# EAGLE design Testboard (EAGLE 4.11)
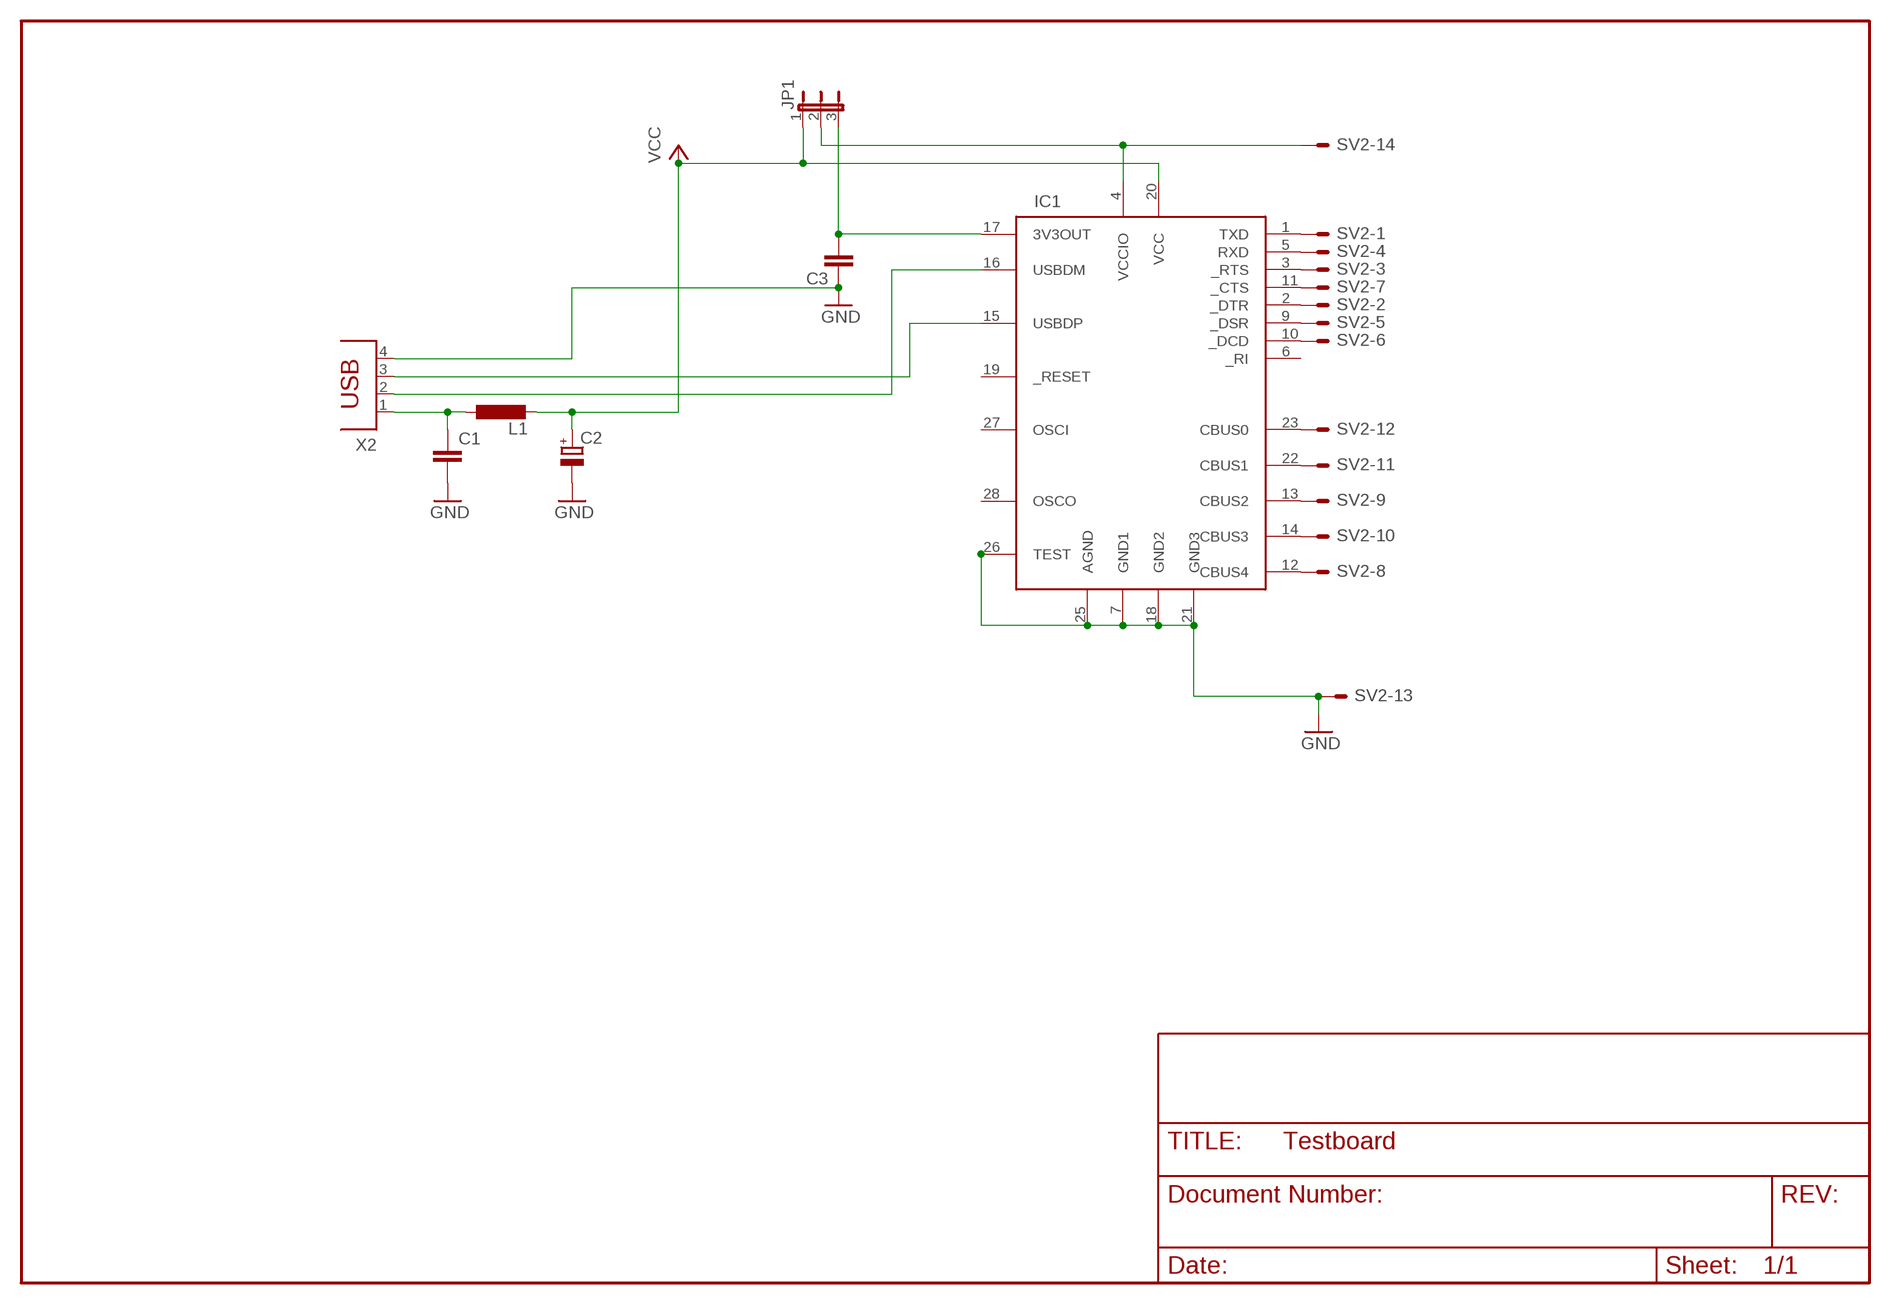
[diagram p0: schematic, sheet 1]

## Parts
C1  C-EUC0805  [C0805]
C2  CPOL-EUE2.5-6  [E2,5-6]
C3  C-EUC0805  [C0805]
IC1  FT232RL  [SSOP28DB]
JP1  JP2E  [JP2]
L1  L-EU0204/7  [0204/7]
SV2  ML14LE  [ML14L]
X2  PN61729  [PN61729]

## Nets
GND: C1.2 C2.- C3.1 IC1.7(GND1) IC1.18(GND2) IC1.21(GND3) IC1.25(AGND) IC1.26(TEST) SV2.13 X2.4
N$1: IC1.1(TXD) SV2.1
N$2: IC1.2(_DTR) SV2.2
N$3: C3.2 IC1.17(3V3OUT) JP1.3
N$4: IC1.16(USBDM) X2.2
N$5: IC1.15(USBDP) X2.3
N$6: IC1.3(_RTS) SV2.3
N$7: IC1.5(RXD) SV2.4
N$8: IC1.9(_DSR) SV2.5
N$9: IC1.10(_DCD) SV2.6
N$10: IC1.11(_CTS) SV2.7
N$11: IC1.12(CBUS4) SV2.8
N$12: IC1.13(CBUS2) SV2.9
N$13: IC1.14(CBUS3) SV2.10
N$14: IC1.22(CBUS1) SV2.11
N$15: IC1.23(CBUS0) SV2.12
N$16: C1.1 L1.1 X2.1
N$17: IC1.4(VCCIO) JP1.2 SV2.14
VCC: C2.+ IC1.20(VCC) JP1.1 L1.2
Unconnected: IC1.6(_RI) IC1.19(_RESET) IC1.27(OSCI) IC1.28(OSCO)

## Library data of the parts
C1 C3 = rcl:C-EU: CAPACITOR, European symbol
C2 = rcl:CPOL-EU: POLARIZED CAPACITOR, European symbol
IC1 = ftdichip:FT232RL: USB UART 4th Generation USB UART (USB <-> Serial) Controller
JP1 = jumper:JP2E: JUMPER
L1 = rcl:L-EU: INDUCTOR, European symbol
SV2 = con-ml:ML14LE: HARTING
X2 = con-berg:PN61729: BERG USB connector

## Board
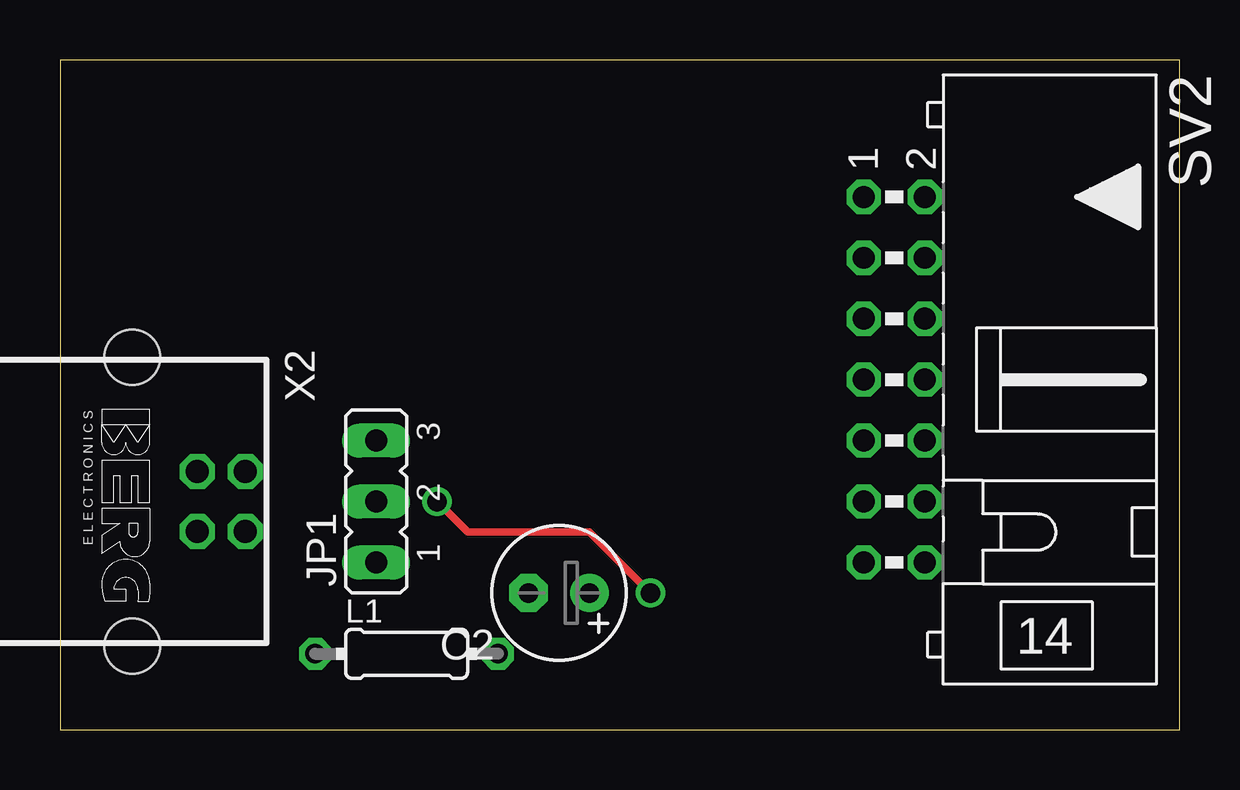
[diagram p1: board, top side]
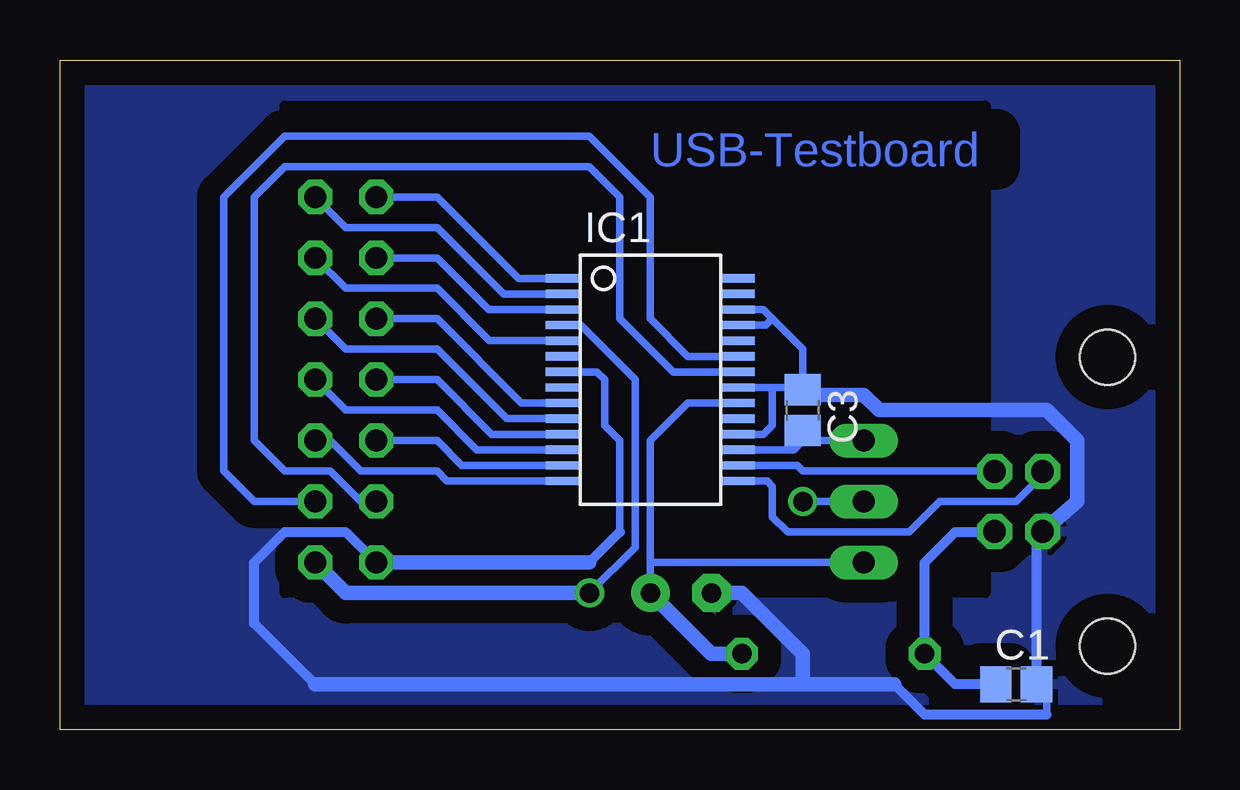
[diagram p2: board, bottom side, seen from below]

Size 46.66 x 27.93 mm. Coordinates in mm from the lower left corner, seen from the top.
Outline: 0,0 46.66,0 46.66,27.93 0,27.93 0,0
Copper layers (1*16): Top 0.035mm / dielectric 1.5mm / Bottom 0.035mm
Design rules "default": minimum track width 10mil, minimum drill 24mil, track to track 38mil, track to pad 38mil, pad to pad 38mil, via to via 38mil, smd to smd 38mil, copper to edge 40mil, drill to drill 8mil, minimum pad ring 10mil, minimum via ring 8mil, stop-mask expansion 4mil, vias tented up to drill 0mil, thermal gap 10mil
bRestrict: area 8.1,5.7 to 37.3,26

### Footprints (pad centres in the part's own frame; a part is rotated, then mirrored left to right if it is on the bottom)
C0805 = smd 1.3 x 1.5: 1 -0.85,0; 2 0.85,0
E2,5-6 = drill 0.813 pad 1.6 round: + -1.27,0 | drill 0.813 pad 1.6 octagon: - 1.27,0
SSOP28DB = smd 0.348 x 1.397: 1 -4.225,-3.656; 2 -3.575,-3.656; 3 -2.925,-3.656; 4 -2.275,-3.656; 5 -1.625,-3.656; 6 -0.975,-3.656; 7 -0.325,-3.656; 8 0.325,-3.656; 9 0.975,-3.656; 10 1.625,-3.656; 11 2.275,-3.656; 12 2.925,-3.656; 13 3.575,-3.656; 14 4.225,-3.656; 15 4.225,3.656; 16 3.575,3.656; 17 2.925,3.656; 18 2.275,3.656; 19 1.625,3.656; 20 0.975,3.656; 21 0.325,3.656; 22 -0.325,3.656; 23 -0.975,3.656; 24 -1.625,3.656; 25 -2.275,3.656; 26 -2.925,3.656; 27 -3.575,3.656; 28 -4.225,3.656
JP2 = drill 0.914 long: 1 -2.54,0; 2 0,0; 3 2.54,0
0204/7 = drill 0.813 octagon: 1 -3.81,0; 2 3.81,0
ML14L = drill 0.914 octagon: 1 -7.62,-1.27; 2 -7.62,1.27; 3 -5.08,-1.27; 4 -5.08,1.27; 5 -2.54,-1.27; 6 -2.54,1.27; 7 0,-1.27; 8 0,1.27; 9 2.54,-1.27; 10 2.54,1.27; 11 5.08,-1.27; 12 5.08,1.27; 13 7.62,-1.27; 14 7.62,1.27
PN61729 = drill 0.95 octagon: 1 1.25,4.71; 2 -1.25,4.71; 3 -1.25,2.71; 4 1.25,2.71 | hole 2.3: -6.02,0; 6.02,0

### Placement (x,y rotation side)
C1  6.82,1.9 0 bottom
C2  20.79,5.71 180 top
C3  15.71,13.33 270 bottom
IC1  22.06,14.6 270 bottom
JP1  13.17,9.52 90 top
L1  14.44,3.17 0 top
SV2  34.76,14.6 270 top
X2  3.01,9.52 270 top

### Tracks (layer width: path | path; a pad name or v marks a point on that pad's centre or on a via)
GND
  Bottom 0.305: 16.98,17.14 15.71,15.87 15.71,14.6 16.04,14.28 16.98,14.28 | 23.33,8.25 23.33,12.06 23.96,12.7 23.96,14.6 24.29,14.93 IC1.7 | IC1.26 17.36,17.52 16.98,17.14 | IC1.25 17.24,16.88 16.98,17.14 | 16.98,14.28 IC1.21 | IC1.18 17.35,12.33 16.98,12.7 16.98,14.28 | 5.55,0.63 5.55,1.9
  Bottom 0.406: X2.4 5.57,8.27 5.55,8.25 5.97,7.83 C1.2 | 24.6,6.98 23.33,8.25 | SV2.13 34.76,8.25 37.3,8.25 38.57,6.98 38.57,4.44 36.03,1.9 | 5.55,0.63 10.63,0.63 11.9,1.9
  Bottom 0.61: X2.4 4.28,9.52 4.28,12.06 5.55,13.33 12.54,13.33 13.17,13.97 15.71,13.97 C3.1 15.71,14.6 | SV2.13 24.6,6.98 | 11.9,1.9 15.71,1.9 | 15.71,1.9 36.03,1.9 | C2.- 18.25,5.71 15.71,3.17 15.71,1.9
  pour Bottom: 0.47,27.3 0.47,0.63 46.19,0.63 46.19,27.3
N$1
  Bottom 0.305: IC1.1 27.55,18.82 30.95,22.22 SV2.1
N$2
  Bottom 0.305: IC1.2 28.17,18.18 30.95,20.95 34.76,20.95 SV2.2
N$3
  Bottom 0.305: IC1.17 16.09,11.68 15.71,12.06 | 15.71,12.06 C3.2 | JP1.3 15.71,12.06
N$4
  Bottom 0.305: IC1.16 15.95,11.03 15.71,10.79 8.09,10.79 8.07,10.77 X2.2
N$5
  Bottom 0.305: 5.57,10.77 5.55,10.79 | X2.3 5.57,10.77 | 5.57,10.77 6.82,9.52 10,9.52 11.27,8.25 16.34,8.25 16.98,8.89 16.98,10.16 17.2,10.38 IC1.15
N$6
  Bottom 0.305: IC1.3 28.79,17.52 30.95,19.68 SV2.3
N$7
  Bottom 0.305: IC1.5 28.77,16.23 30.95,18.41 34.76,18.41 SV2.4
N$8
  Bottom 0.305: IC1.9 27.43,13.62 30.95,17.14 SV2.5
N$9
  Bottom 0.305: IC1.10 28.05,12.98 30.95,15.87 34.76,15.87 SV2.6
N$10
  Bottom 0.305: IC1.11 28.67,12.33 30.95,14.6 SV2.7
N$11
  Bottom 0.305: IC1.12 29.29,11.68 30.95,13.33 34.76,13.33 SV2.8
N$12
  Bottom 0.305: IC1.13 29.91,11.03 30.95,12.06 SV2.9
N$13
  Bottom 0.305: IC1.14 30.54,10.38 30.95,10.79 34.12,10.79 35.39,12.06 SV2.10
N$14
  Bottom 0.305: IC1.22 21.11,14.93 23.33,17.14 23.33,22.22 24.6,23.49 37.3,23.49 38.57,22.22 38.57,12.06 37.3,10.79 35.39,10.79 34.12,9.52 SV2.11
N$15
  Bottom 0.305: IC1.23 20.49,15.58 22.06,17.14 22.06,22.22 24.6,24.76 37.3,24.76 39.84,22.22 39.84,10.79 38.57,9.52 SV2.12
N$16
  Bottom 0.406: C1.1 9.36,1.9 L1.1 10.63,6.98 9.36,8.25 8.09,8.25 8.07,8.27 X2.1
N$17  (via drill 0.81)
  Top 0.305: v15.71,9.52 16.98,8.25 22.06,8.25 v24.6,5.71
  Bottom 0.305: IC1.4 24.97,16.88 22.7,14.6 22.7,7.62 v24.6,5.71 | JP1.2 v15.71,9.52
  Bottom 0.61: v24.6,5.71 34.76,5.71 SV2.14
VCC
  Bottom 0.305: 22.06,6.98 C2.+ | 22.06,6.98 22.06,12.06 20.49,13.62 IC1.20 | JP1.1 22.06,6.98
  Bottom 0.61: L1.2 19.52,3.17 C2.+

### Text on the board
Bottom: USB-Testboard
